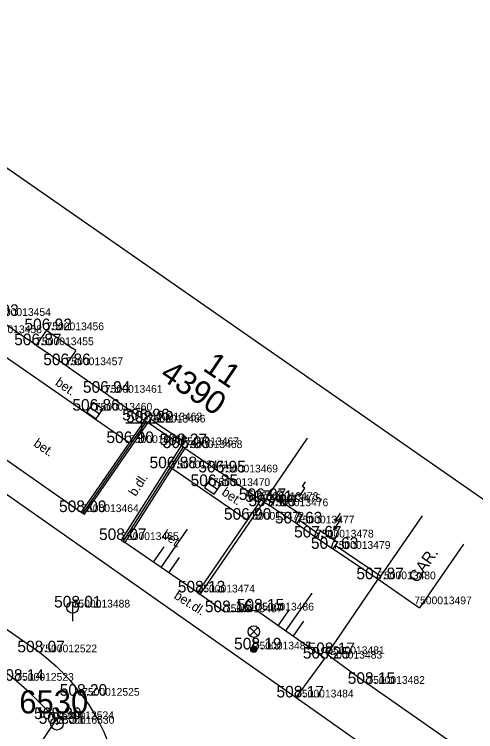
# Model space of a CAD drawing. Extents: x -669251 to -668549, y -1128351 to -1127698.
# Drawn here: x -668858.22 to -668828.37, y -1127819.96 to -1127773.58 of the extents above; entities that cross this region are included whole.
import ezdxf

# ---------------------------------------------------------------- set-up
doc = ezdxf.new("R2010")
doc.units = 0
for name, color, linetype in [('Vrstva 1', 7, 'Continuous'), ('Vrstva 10', 7, 'Continuous'), ('Vrstva 11', 7, 'Continuous'), ('Vrstva 15', 7, 'Continuous'), ('Vrstva 2', 7, 'Continuous'), ('Vrstva 24', 7, 'Continuous'), ('Vrstva 27', 7, 'Continuous'), ('Vrstva 3', 7, 'Continuous'), ('Vrstva 33', 7, 'Continuous'), ('Vrstva 40', 7, 'Continuous'), ('Vrstva 41', 7, 'Continuous'), ('Vrstva 43', 7, 'Continuous'), ('Vrstva 44', 7, 'Continuous'), ('Vrstva 5', 7, 'Continuous'), ('Vrstva 6', 7, 'Continuous'), ('Vrstva 60', 7, 'Continuous'), ('Vrstva 61', 7, 'Continuous'), ('Vrstva 63', 7, 'Continuous'), ('Vrstva 7', 7, 'Continuous'), ('Vrstva 8', 7, 'Continuous'), ('Vrstva 9', 7, 'Continuous')]:
    doc.layers.add(name, color=color, linetype=linetype)

msp = doc.modelspace()

# ---------------------------------------------------------------- linework, layer by layer
at = {"layer": 'Vrstva 1'}
for p, q in [((-668856.139, -1127793.999), (-668856.139, -1127793.999)), ((-668856.805, -1127794.969), (-668856.805, -1127794.969)), ((-668854.9, -1127796.262), (-668854.9, -1127796.262)), ((-668852.352, -1127798.045), (-668852.352, -1127798.045)), ((-668853.017, -1127799.202), (-668853.017, -1127799.202)), ((-668849.791, -1127799.829), (-668849.791, -1127799.829)), ((-668849.573, -1127799.97), (-668849.573, -1127799.97)), ((-668850.796, -1127801.297), (-668850.796, -1127801.297)), ((-668847.406, -1127801.435), (-668847.406, -1127801.435)), ((-668847.186, -1127801.623), (-668847.186, -1127801.623)), ((-668848.044, -1127802.927), (-668848.044, -1127802.927)), ((-668844.88, -1127803.197), (-668844.88, -1127803.197)), ((-668845.389, -1127804.078), (-668845.389, -1127804.078)), ((-668842.265, -1127804.976), (-668842.265, -1127804.976)), ((-668842.088, -1127805.108), (-668842.088, -1127805.108)), ((-668841.626, -1127805.384), (-668841.626, -1127805.384)), ((-668853.892, -1127805.762), (-668853.892, -1127805.762)), ((-668843.194, -1127806.255), (-668843.194, -1127806.255)), ((-668839.933, -1127806.495), (-668839.933, -1127806.495)), ((-668851.307, -1127807.568), (-668851.307, -1127807.568)), ((-668838.69, -1127807.406), (-668838.69, -1127807.406)), ((-668837.602, -1127808.139), (-668837.602, -1127808.139)), ((-668834.672, -1127810.105), (-668834.672, -1127810.105)), ((-668846.369, -1127810.959), (-668846.369, -1127810.959)), ((-668854.45, -1127811.932), (-668854.45, -1127811.932)), ((-668832.339, -1127811.722), (-668832.339, -1127811.722)), ((-668844.597, -1127812.235), (-668844.597, -1127812.235)), ((-668842.554, -1127812.126), (-668842.554, -1127812.126)), ((-668842.727, -1127814.643), (-668842.727, -1127814.643)), ((-668856.591, -1127814.83), (-668856.591, -1127814.83)), ((-668838.139, -1127815.236), (-668838.139, -1127815.236)), ((-668837.974, -1127814.946), (-668837.974, -1127814.946)), ((-668858.095, -1127816.67), (-668858.095, -1127816.67)), ((-668835.374, -1127816.87), (-668835.374, -1127816.87)), ((-668853.835, -1127817.637), (-668853.835, -1127817.637)), ((-668839.985, -1127817.748), (-668839.985, -1127817.748)), ((-668855.496, -1127819.148), (-668855.496, -1127819.148)), ((-668855.468, -1127819.451), (-668855.468, -1127819.451))]:
    msp.add_line(p, q, dxfattribs=at)
at = {"layer": 'Vrstva 10'}
for p, q in [((-668907.589, -1127779.058), (-668856.591, -1127814.83)), ((-668849.791, -1127799.829), (-668850.803, -1127801.292)), ((-668853.674, -1127805.903), (-668849.573, -1127799.97)), ((-668850.803, -1127801.292), (-668853.892, -1127805.762)), ((-668847.406, -1127801.435), (-668851.307, -1127807.568)), ((-668847.186, -1127801.623), (-668848.024, -1127802.941)), ((-668848.024, -1127802.941), (-668851.071, -1127807.73)), ((-668842.265, -1127804.976), (-668843.159, -1127806.279)), ((-668846.19, -1127811.088), (-668842.088, -1127805.108)), ((-668853.892, -1127805.762), (-668853.674, -1127805.903)), ((-668843.159, -1127806.279), (-668846.369, -1127810.959)), ((-668851.307, -1127807.568), (-668851.071, -1127807.73)), ((-668846.369, -1127810.959), (-668851.071, -1127807.73)), ((-668846.369, -1127810.959), (-668846.19, -1127811.088)), ((-668844.597, -1127812.235), (-668846.19, -1127811.088)), ((-668842.554, -1127812.126), (-668844.597, -1127812.235)), ((-668838.139, -1127815.236), (-668842.554, -1127812.126)), ((-668839.985, -1127817.748), (-668838.139, -1127815.236)), ((-668839.985, -1127817.748), (-668808.868, -1127839.638)), ((-668855.496, -1127819.148), (-668862.836, -1127829.926))]:
    msp.add_line(p, q, dxfattribs=at)
for points in [[(-668887.358, -1127764.319), (-668889.806, -1127767.851), (-668892.255, -1127771.383), (-668892.781, -1127772.263), (-668893.106, -1127772.966), (-668893.497, -1127774.06), (-668893.788, -1127775.168), (-668893.877, -1127775.9), (-668893.859, -1127776.462), (-668893.721, -1127777.31), (-668893.483, -1127778.143), (-668893.153, -1127779.116), (-668892.872, -1127779.835), (-668892.624, -1127780.346), (-668892.409, -1127780.705), (-668892.029, -1127781.19), (-668891.565, -1127781.595), (-668865.775, -1127799.672), (-668839.985, -1127817.748)], [(-668879.97, -1127801.247), (-668874.443, -1127805.031), (-668870.265, -1127807.831), (-668867.147, -1127809.949), (-668864.831, -1127811.565), (-668861.415, -1127814.059), (-668859.741, -1127815.348), (-668858.095, -1127816.67), (-668857.422, -1127817.261), (-668856.456, -1127818.201), (-668855.496, -1127819.148)], [(-668856.591, -1127814.83), (-668856.366, -1127815.005), (-668856.141, -1127815.18), (-668855.507, -1127815.725), (-668854.643, -1127816.636), (-668853.835, -1127817.637), (-668853.433, -1127818.193), (-668852.818, -1127819.2), (-668852.425, -1127819.981), (-668851.928, -1127821.193), (-668851.527, -1127822.448), (-668851.211, -1127823.76), (-668851.062, -1127824.77), (-668851.02, -1127825.528), (-668851.038, -1127826.091), (-668851.155, -1127826.917), (-668851.399, -1127827.709), (-668852.43, -1127830.25), (-668853.46, -1127832.792)]]:
    msp.add_lwpolyline(points, dxfattribs=at)
at = {"layer": 'Vrstva 11'}
for p, q in [((-668850.803, -1127801.292), (-668862.926, -1127792.871)), ((-668865.981, -1127797.318), (-668853.892, -1127805.762)), ((-668843.159, -1127806.279), (-668848.024, -1127802.941))]:
    msp.add_line(p, q, dxfattribs=at)
at = {"layer": 'Vrstva 15'}
for p, q in [((-668848.719, -1127809.345), (-668847.021, -1127806.872)), ((-668849.214, -1127809.005), (-668848.534, -1127808.016)), ((-668848.225, -1127809.685), (-668847.545, -1127808.696)), ((-668840.67, -1127813.453), (-668838.942, -1127811)), ((-668841.161, -1127813.108), (-668840.47, -1127812.126)), ((-668840.18, -1127813.799), (-668839.488, -1127812.818))]:
    msp.add_line(p, q, dxfattribs=at)
at = {"layer": 'Vrstva 24'}
for p, q in [((-668841.626, -1127805.384), (-668841.28, -1127804.857)), ((-668841.28, -1127804.857), (-668839.588, -1127805.968)), ((-668841.626, -1127805.384), (-668839.934, -1127806.494)), ((-668839.588, -1127805.968), (-668839.934, -1127806.494)), ((-668837.144, -1127805.836), (-668837.493, -1127806.355)), ((-668837.076, -1127806.184), (-668837.565, -1127806.91)), ((-668837.493, -1127806.355), (-668837.076, -1127806.184)), ((-668837.52, -1127806.645), (-668837.565, -1127806.91)), ((-668837.565, -1127806.91), (-668837.337, -1127806.768)), ((-668838.69, -1127807.406), (-668838.399, -1127806.975)), ((-668838.399, -1127806.975), (-668837.312, -1127807.707)), ((-668838.69, -1127807.406), (-668837.603, -1127808.138)), ((-668837.312, -1127807.707), (-668837.603, -1127808.138))]:
    msp.add_line(p, q, dxfattribs=at)
msp.add_lwpolyline([(-668840.089, -1127804.886), (-668839.886, -1127804.579), (-668839.733, -1127804.679), (-668839.43, -1127804.218), (-668839.582, -1127804.116), (-668839.381, -1127803.808)], dxfattribs=at)
at = {"layer": 'Vrstva 27'}
for p, q in [((-668853.327, -1127798.991), (-668852.707, -1127799.413)), ((-668845.699, -1127803.867), (-668845.079, -1127804.289)), ((-668854.45, -1127811.557), (-668854.45, -1127812.807))]:
    msp.add_line(p, q, dxfattribs=at)
for points in [[(-668853.538, -1127799.3), (-668852.918, -1127799.722), (-668852.495, -1127799.103), (-668853.115, -1127798.68)], [(-668845.91, -1127804.176), (-668845.29, -1127804.598), (-668844.867, -1127803.979), (-668845.487, -1127803.556)]]:
    msp.add_lwpolyline(points, close=True, dxfattribs=at)
msp.add_circle((-668854.45, -1127811.932), 0.375, dxfattribs=at)
at = {"layer": 'Vrstva 33'}
for p, q in [((-668842.992, -1127813.228), (-668842.462, -1127813.758)), ((-668842.992, -1127813.758), (-668842.462, -1127813.228)), ((-668842.727, -1127814.643), (-668842.727, -1127813.868))]:
    msp.add_line(p, q, dxfattribs=at)
for centre, radius in [((-668842.727, -1127813.493), 0.375), ((-668842.727, -1127814.643), 0.2), ((-668842.727, -1127814.643), 0.18), ((-668842.727, -1127814.643), 0.16), ((-668842.727, -1127814.643), 0.14), ((-668842.727, -1127814.643), 0.12), ((-668842.727, -1127814.643), 0.1), ((-668842.727, -1127814.643), 0.08), ((-668842.727, -1127814.643), 0.06), ((-668842.727, -1127814.643), 0.04), ((-668842.727, -1127814.643), 0.02)]:
    msp.add_circle(centre, radius, dxfattribs=at)
at = {"layer": 'Vrstva 5'}
for p, q in [((-668856.139, -1127793.999), (-668856.805, -1127794.969)), ((-668856.139, -1127793.999), (-668855.934, -1127794.142)), ((-668856.805, -1127794.969), (-668857.301, -1127794.631)), ((-668856.805, -1127794.969), (-668854.9, -1127796.262)), ((-668854.241, -1127795.32), (-668854.446, -1127795.177)), ((-668854.241, -1127795.32), (-668854.9, -1127796.262)), ((-668854.9, -1127796.262), (-668854.408, -1127796.606)), ((-668852.353, -1127798.044), (-668852.106, -1127798.216)), ((-668850.078, -1127799.629), (-668849.791, -1127799.829)), ((-668849.791, -1127799.829), (-668849.573, -1127799.97)), ((-668849.416, -1127799.738), (-668849.573, -1127799.97)), ((-668849.085, -1127799.962), (-668849.416, -1127799.738)), ((-668849.573, -1127799.97), (-668847.406, -1127801.435)), ((-668847.581, -1127800.979), (-668847.249, -1127801.203)), ((-668847.249, -1127801.203), (-668847.406, -1127801.435)), ((-668839.276, -1127800.974), (-668841.947, -1127804.901)), ((-668847.406, -1127801.435), (-668847.186, -1127801.623)), ((-668847.186, -1127801.623), (-668846.938, -1127801.792)), ((-668844.632, -1127803.366), (-668844.88, -1127803.197)), ((-668842.088, -1127805.108), (-668842.265, -1127804.976)), ((-668841.947, -1127804.901), (-668842.088, -1127805.108)), ((-668831.824, -1127805.996), (-668834.53, -1127809.9)), ((-668829.162, -1127807.84), (-668832.01, -1127811.95)), ((-668834.53, -1127809.9), (-668834.672, -1127810.105)), ((-668834.672, -1127810.105), (-668834.343, -1127810.333)), ((-668832.339, -1127811.722), (-668832.01, -1127811.95))]:
    msp.add_line(p, q, dxfattribs=at)
at = {"layer": 'Vrstva 6'}
for p, q in [((-668859.329, -1127793.247), (-668857.301, -1127794.631)), ((-668855.934, -1127794.142), (-668854.446, -1127795.177)), ((-668854.408, -1127796.606), (-668852.353, -1127798.044)), ((-668852.106, -1127798.216), (-668850.078, -1127799.629)), ((-668849.085, -1127799.962), (-668847.581, -1127800.979)), ((-668846.938, -1127801.792), (-668844.88, -1127803.197)), ((-668844.632, -1127803.366), (-668842.265, -1127804.976)), ((-668834.343, -1127810.333), (-668832.339, -1127811.722))]:
    msp.add_line(p, q, dxfattribs=at)
at = {"layer": 'Vrstva 60'}
msp.add_lwpolyline([(-668982.815, -1128190.464), (-668751.689, -1127857.889), (-668981.618, -1127698.099), (-669212.743, -1128030.674)], close=True, dxfattribs=at)
at = {"layer": 'Vrstva 61'}
for p, q in [((-668850, -1127799), (-668850, -1127801)), ((-668851, -1127800), (-668849, -1127800))]:
    msp.add_line(p, q, dxfattribs=at)
at = {"layer": 'Vrstva 63'}
for radius in [0.412, 0.412, 0.05, 0.05]:
    msp.add_circle((-668855.468, -1127819.451), radius, dxfattribs=at)
at = {"layer": 'Vrstva 7'}
for p, q in [((-668841.489, -1127805.175), (-668841.947, -1127804.901)), ((-668842.088, -1127805.108), (-668841.626, -1127805.384)), ((-668838.55, -1127807.199), (-668839.796, -1127806.285)), ((-668839.933, -1127806.495), (-668838.69, -1127807.406)), ((-668837.602, -1127808.139), (-668834.672, -1127810.105)), ((-668834.53, -1127809.9), (-668837.463, -1127807.931)), ((-668837.974, -1127814.946), (-668834.672, -1127810.105)), ((-668824.114, -1127824.707), (-668835.374, -1127816.87))]:
    msp.add_line(p, q, dxfattribs=at)
at = {"layer": 'Vrstva 8'}
msp.add_line((-668837.974, -1127814.946), (-668835.374, -1127816.87), dxfattribs=at)
at = {"layer": 'Vrstva 9'}
for p, q in [((-668849.684, -1127799.903), (-668853.785, -1127805.836)), ((-668847.279, -1127801.516), (-668851.18, -1127807.649))]:
    msp.add_line(p, q, dxfattribs=at)

# ---------------------------------------------------------------- texts
at = {"layer": 'Vrstva 2'}
for s, p in [('7500013454', (-668859.577, -1127793.078)), ('7500013458', (-668860.155, -1127794.19)), ('7500013456', (-668856.139, -1127793.999)), ('7500013455', (-668856.805, -1127794.969)), ('7500013457', (-668854.9, -1127796.262)), ('7500013461', (-668852.352, -1127798.045)), ('7500013460', (-668853.017, -1127799.202)), ('7500013462', (-668849.791, -1127799.829)), ('7500013466', (-668849.573, -1127799.97)), ('7500013463', (-668850.796, -1127801.297)), ('7500013467', (-668847.406, -1127801.435)), ('7500013468', (-668847.186, -1127801.623)), ('7500013471', (-668848.044, -1127802.927)), ('7500013469', (-668844.88, -1127803.197)), ('7500013470', (-668845.389, -1127804.078)), ('7500013473', (-668842.265, -1127804.976)), ('7500013475', (-668842.088, -1127805.108)), ('7500013476', (-668841.626, -1127805.384)), ('7500013464', (-668853.892, -1127805.762)), ('7500013472', (-668843.194, -1127806.255)), ('7500013477', (-668839.933, -1127806.495)), ('7500013465', (-668851.307, -1127807.568)), ('7500013478', (-668838.69, -1127807.406)), ('7500013479', (-668837.602, -1127808.139)), ('7500013480', (-668834.672, -1127810.105)), ('7500013474', (-668846.369, -1127810.959)), ('7500013488', (-668854.45, -1127811.932)), ('7500013497', (-668832.339, -1127811.722)), ('7500013487', (-668844.597, -1127812.235)), ('7500013486', (-668842.554, -1127812.126)), ('7500013485', (-668842.727, -1127814.643)), ('7500012522', (-668856.591, -1127814.83)), ('7500013483', (-668838.139, -1127815.236)), ('7500013481', (-668837.974, -1127814.946)), ('7500012523', (-668858.095, -1127816.67)), ('7500013482', (-668835.374, -1127816.87)), ('7500012525', (-668853.835, -1127817.637)), ('7500013484', (-668839.985, -1127817.748)), ('7500012524', (-668855.496, -1127819.148)), ('7500016530', (-668855.468, -1127819.451))]:
    msp.add_text(s, height=0.5, dxfattribs=at).set_placement(p)
at = {"layer": 'Vrstva 3'}
for s, p in [('506.93 ', (-668861.008, -1127793.078)), ('506.92 ', (-668857.57, -1127793.999)), ('506.87 ', (-668858.234, -1127794.969)), ('506.86 ', (-668856.352, -1127796.262)), ('506.94 ', (-668853.783, -1127798.045)), ('506.86 ', (-668854.469, -1127799.202)), ('506.96 ', (-668851.245, -1127799.829)), ('508.22 ', (-668850.988, -1127799.97)), ('506.90 ', (-668852.262, -1127801.297)), ('508.27 ', (-668848.821, -1127801.435)), ('506.93 ', (-668848.617, -1127801.623)), ('506.88 ', (-668849.473, -1127802.927)), ('506.95 ', (-668846.311, -1127803.197)), ('506.85 ', (-668846.818, -1127804.078)), ('506.97 ', (-668843.696, -1127804.976)), ('507.61 ', (-668843.28, -1127805.108)), ('508.09 ', (-668855.332, -1127805.762)), ('507.66 ', (-668843.078, -1127805.384)), ('506.90 ', (-668844.66, -1127806.255)), ('507.63 ', (-668841.362, -1127806.495)), ('508.07 ', (-668852.743, -1127807.568)), ('507.67 ', (-668840.119, -1127807.406)), ('507.63 ', (-668839.031, -1127808.139)), ('507.87 ', (-668836.087, -1127810.105)), ('508.13 ', (-668847.643, -1127810.959)), ('508.01 ', (-668855.65, -1127811.932)), ('508.16 ', (-668845.893, -1127812.235)), ('508.15 ', (-668843.828, -1127812.126)), ('508.07 ', (-668858.027, -1127814.83)), ('508.19 ', (-668844.003, -1127814.643)), ('508.17 ', (-668839.248, -1127814.946)), ('508.25 ', (-668839.554, -1127815.236)), ('508.14 ', (-668859.369, -1127816.67)), ('508.15 ', (-668836.648, -1127816.87)), ('508.20 ', (-668855.286, -1127817.637)), ('508.17 ', (-668841.259, -1127817.748)), ('508.30 ', (-668856.947, -1127819.148)), ('508.31 ', (-668856.646, -1127819.451))]:
    msp.add_text(s, height=0.75, dxfattribs=at).set_placement(p)
at = {"layer": 'Vrstva 40'}
for s, rotation, p in [('bet.', 325.522, (-668855.624, -1127797.506)), ('bet.', 325.522, (-668857.032, -1127801.451)), ('b.dl.', 57.5409, (-668850.371, -1127804.792)), ('bet.', 325.5426, (-668844.858, -1127804.6)), ('bet.', 325.522, (-668848.726, -1127807.344)), ('bet.dl.', 327.238, (-668847.943, -1127811.3))]:
    msp.add_text(s, height=0.6, rotation=rotation, dxfattribs=at).set_placement(p)
at = {"layer": 'Vrstva 41'}
msp.add_text('GAR.', height=0.75, rotation=55.2742, dxfattribs=at).set_placement((-668832.149, -1127810.395))
at = {"layer": 'Vrstva 43'}
msp.add_text('4390', height=1.5, rotation=325.9393, dxfattribs=at).set_placement((-668848.886, -1127797.079))
at = {"layer": 'Vrstva 44'}
msp.add_text('11', height=1.5, rotation=325.9393, dxfattribs=at).set_placement((-668846.093, -1127796.553))
at = {"layer": 'Vrstva 63'}
msp.add_text('6530', height=1.5, dxfattribs=at).set_placement((-668857.904, -1127818.786))
msp.add_text('6530', height=1.5, dxfattribs=at).set_placement((-668857.904, -1127818.786))

doc.saveas('drawing.dxf')
